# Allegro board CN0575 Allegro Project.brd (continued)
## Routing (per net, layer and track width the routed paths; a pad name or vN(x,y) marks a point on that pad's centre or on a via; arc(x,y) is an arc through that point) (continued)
UNNAMED_9_ADLTC9111_I40_LGATE2: length 20.7
  TOP w0.203: v1(22.89,14.77) 23.44,14.77 23.62,14.59 23.62,12.07 24.31,11.38 Q4.4 ; v1(20.38,24.58) 20.38,22.74 20.58,22.54 U1.8
  L3 PWR w0.203: v1(20.38,24.58) 20.37,24.58 20.37,16.46 22.06,14.77 v1(22.89,14.77)
UNNAMED_9_ADLTC9111_I40_SCCP: length 31
  TOP w0.203: U1.7 21.2,24.14 v1(21.65,24.58)
  L3 PWR w0.203: v1(21.65,24.58) 21.79,24.44 21.79,19.42 24.05,17.16 24.05,13.16 v1(24.57,12.65)
  BOTTOM w0.203: Q2.1 30.56,13.69 30.28,13.41 25.33,13.41 v1(24.57,12.65) 24.57,10.36 25.13,9.8 Q3.1
UNNAMED_9_CAP_I53_N1: length 1.6
  TOP w0.203: R16.2 C10.1
UNNAMED_9_CAP_I54_N1: length 2.6
  BOTTOM w0.635: R15.2 C9.1
UNNAMED_9_CAP_I80_N1: length 1.2
  BOTTOM w0.203: C12.1 18.65,15.48 R19.2
UNNAMED_9_CAPP_I72_N1: length 5.2
  TOP w0.762: C16.P 17.84,11.22 16.91,12.15 R20.2
UNNAMED_9_RES_I96_N1: length 2.3
  BOTTOM w0.203: Q2.2 28.42,16.76 R17.1
UNNAMED_9_RES_I97_N1: length 2.2
  BOTTOM w0.203: Q3.2 30.51,11.63 R18.1
UNNAMED_10_ADIN1110V2_I97_CEXT2: length 1.6
  TOP w0.203: C39.1 32.61,38.66 U3.19
UNNAMED_10_ADIN1110V2_I97_CEXT3: length 2.4
  TOP w0.203: C40.1 34.66,38.73 33.36,38.73 33.11,38.99 U3.20
UNNAMED_10_ADIN1110V2_I97_CLK25REF: length 51.5
  TOP w0.203: v1(53.78,34.68) 53.78,34.65 55.05,33.38 59.23,33.38 60.51,34.65 60.51,43.75 61.09,44.32 CLKOUT.1 ; U3.7 26.78,41.36 26.66,41.47 v1(26.22,41.47)
  L3 PWR w0.203: v1(26.22,41.47) 26.73,41.47 29.01,39.19 31.66,39.19 35.35,35.51 52.95,35.51 v1(53.78,34.68)
UNNAMED_10_ADIN1110V2_I97_DLDO1P1: length 39.5
  TOP w0.229: v1(34.54,41.09) 34.3,40.86 U3.23
  TOP w0.254: U3.24 34.27,41.36 v1(34.54,41.09)
  TOP w0.508: v1(34.54,41.09) 35.33,41.09 35.84,41.6 C32.1 ; UNK1.1V.1 61.48,47.62 60.65,48.46 v1(39.43,48.46)
  BOTTOM w0.508: v1(39.43,48.46) 39.43,42.67 38.23,41.47 37.04,41.47 C33.1 35.31,40.23 35.31,40.59 34.8,41.09 v1(34.54,41.09)
UNNAMED_10_ADIN1110V2_I97_LED0: length 38.3
  TOP w0.203: v1(26.57,43.98) 26.86,43.69 27.12,43.69 27.45,43.36 U3.3 ; LED0.C v1(54.03,40.46)
  L3 PWR w0.203: v1(54.03,40.46) 49.84,36.27 35.66,36.27 31.85,40.08 29.65,40.08 26.57,43.16 v1(26.57,43.98)
  BOTTOM w0.203: v1(26.57,43.98) 27.4,43.16 R31.2
UNNAMED_10_ADIN1110V2_I97_LED1: length 39.4
  TOP w0.203: U3.6 27.09,41.86 26.71,42.24 v1(26.22,42.24) ; LED1.C v1(54.03,38.68)
  L3 PWR w0.203: v1(26.22,42.24) 26.73,42.24 29.26,39.7 31.69,39.7 35.5,35.89 51.24,35.89 v1(54.03,38.68)
  BOTTOM w0.203: 26.87,40.57 27.18,40.88 27.18,40.98 ; 26.87,40.57 26.87,40.68 27.18,40.98 ; 26.87,40.57 26.38,40.08 26.21,40.08 R33.2 ; 27.18,40.98 27.18,41.97 26.91,42.24 v1(26.22,42.24)
UNNAMED_10_ADIN1110V2_I97_TEST1: length 3.2
  TOP w0.203: R29.2 34.92,43.88 34.91,43.88 34.48,43.45 34.48,42.63 34.21,42.36 U3.26
UNNAMED_10_DIOLED_I154_P: length 2
  TOP w0.203: LED0.A v1(58.42,40.46)
  BOTTOM w0.203: v1(58.42,40.46) R30.2
UNNAMED_10_DIOLED_I156_P: length 2
  TOP w0.203: LED1.A v1(58.42,38.68)
  BOTTOM w0.203: v1(58.42,38.68) R32.2
UNNAMED_10_NC2P_I58_N2: length 4.1
  BOTTOM w0.203: R34.2 35.31,45.15 35.31,48.23 35.52,48.43 JP3.2
UNNAMED_10_NC2P_I158_N2: length 2.6
  BOTTOM w0.203: R35.2 19.63,41.76 19.63,43.4 19.84,43.6 JP4.2
UNNAMED_10_NC2P_I159_N2: length 2.5
  BOTTOM w0.203: JP5.2 19.63,34.63 19.63,36.11 R36.2
UNNAMED_11_ADT75_I4_A0: length 18.2
  TOP w0.203: U4.7 v1(44.44,46.75)
  BOTTOM w0.203: JP8.2 40.77,35.17 40.41,35.54 40.41,41.1 40,41.51 40,45.88 40.87,46.75 v1(44.44,46.75)
UNNAMED_11_ADT75_I4_A1: length 9.1
  TOP w0.203: v1(44.88,43.64) 45.16,43.92 45.16,45.35 U4.6
  BOTTOM w0.203: v1(44.88,43.64) 44.88,39.78 44.28,39.18 JP7.2
UNNAMED_11_ADT75_I4_A2: length 9.5
  TOP w0.203: U4.5 45.67,45.36 45.67,43.48 44.48,42.3 42.32,42.3 v1(40.56,44.06)
  BOTTOM w0.203: JP6.2 v1(40.56,44.06)
UNNAMED_11_NC3PJMPR_I11_B: length 1.9
  BOTTOM w0.203: R42.1 43.67,36.01 JP8.3
UNNAMED_11_NC3PJMPR_I12_B: length 1.8
  BOTTOM w0.203: JP7.3 R41.1
UNNAMED_11_NC3PJMPR_I13_B: length 1.9
  BOTTOM w0.203: JP6.3 43.67,44.89 R40.1
VPD: length 29.4
  TOP w0.203: 25.36,21.54 24.8,21.54 24.8,21.54 U1.3 ; 25.36,21.54 25.96,20.94 C11.1 26.18,20.98 25.62,21.54 25.36,21.54
  TOP w0.762: C11.1 26.22,20.94 26.27,20.99 R16.1 29.2,20.99 29.96,20.23 v1(29.96,19.12) v1(29.96,18.49) 29.96,18.37 30.03,18.3 30.03,18.11 29.64,17.73 D3.C 29.52,17.73 29.52,17.85 29.27,18.1 29.27,18.3 29.33,18.35 v1(29.33,18.49) v1(29.33,19.12) 29.33,20.04 29.27,20.09 29.27,20.42 28.82,20.86 ; v1(29.33,8.07) 29.33,8.52 29.64,8.84 ; 29.64,8.84 29.96,8.52 v1(29.96,8.07) ; 29.64,8.84 D4.C
  BOTTOM w1.524: 17.02,9.78 D5.C 21.95,9.78 23.99,7.73 29.67,7.73
  vias: v1(29.33,7.44) v1(29.96,7.44)
XTALI: length 6
  TOP w0.203: Y1.1 22.6,41.3 23.02,40.89 24.98,40.89 C36.1 25.58,40.86 U3.8
XTALO: length 4.5
  TOP w0.203: U3.9 25.53,40.36 C37.1 23.67,40.1 Y1.3

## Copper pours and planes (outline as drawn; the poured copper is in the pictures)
3V3_POWER on BOTTOM: 54.48,41.48 54.48,35.89 56.95,35.89 56.95,41.48
3V3_POWER on L3 PWR: 58.9,32.23 39.88,32.23 37.31,29.67 1.65,29.67 1.65,55.63 64.36,55.63 64.36,34.9 61.57,34.9
5V_POWER on TOP: 9.53,41.05 5.44,41.05 5.01,41.47 5.01,48.06 5.38,48.44 10.11,48.44 10.16,48.49 10.16,49.94 10.41,50.19 12.04,50.19 12.5,49.73 12.5,41.47 12.12,41.09 12.12,39.22 10.24,39.22 10.22,39.24 10.22,40.35
5V_POWER on BOTTOM: 6.6,47.12 6.6,48.64 10.79,48.64 10.92,48.51 10.92,47.12 10.79,46.99 6.73,46.99
5V_POWER on BOTTOM: 8.25,49.91 8.25,49.15 8.13,49.02 8.13,48.54 6.6,48.54 6.6,54.48 7.37,55.24 12.06,55.24 12.32,54.99 12.32,53.59 12.06,53.34 8,53.34 7.75,53.09 7.75,50.42
GND on TOP: 42.82,1.27 1.27,1.27 1.27,27.61 1.27,27.64 37.31,27.64 38.48,26.47 38.48,20.98 39.83,19.63 42.82,19.63
GND on BOTTOM: 1.27,1.27 1.27,27.61 1.27,27.64 37.31,27.64 38.48,26.47 38.48,20.98 39.83,19.63 40.79,19.63 40.79,15.75 37.72,15.75 37.21,15.24 37.21,11.51 37.74,10.97 40.79,10.97 40.79,1.27
GND on L2 GND: 38.48,26.47 38.48,20.98 39.83,19.63 42.82,19.63 42.82,1.27 1.27,1.27 1.27,27.61 1.27,27.64 37.31,27.64
GND on L3 PWR: 1.27,1.27 1.27,27.62 1.27,27.64 37.31,27.64 38.48,26.47 38.48,20.98 39.83,19.63 42.82,19.63 42.82,1.27 40.31,1.27
GND_EARTH on TOP: 40.64,30.38 59.64,30.38 62.31,33.05 64.74,33.05 64.74,1.27 44.7,1.27 44.7,20.8 43.99,21.51 40.77,21.51 40.36,21.92 40.36,30.1
GND_EARTH on BOTTOM: 59.64,30.38 62.31,33.05 64.77,33.05 64.77,1.27 44.96,1.27 44.7,1.27 44.7,20.8 43.99,21.51 40.77,21.51 40.36,21.92 40.36,30.1 40.64,30.38 ; 1 cut-out
GND_EARTH on L2 GND: 40.64,30.38 59.64,30.38 62.31,33.05 64.77,33.05 64.77,1.27 44.7,1.27 44.7,20.8 43.99,21.51 40.77,21.51 40.36,21.92 40.36,30.1 ; 1 cut-out
GND_EARTH on L3 PWR: 40.64,30.38 59.64,30.38 62.31,33.05 64.77,33.05 64.77,1.27 44.7,1.27 44.7,20.8 43.99,21.51 40.77,21.51 40.36,21.92 40.36,30.1 ; 1 cut-out
GND_ISO on TOP: 1.27,56.01 64.77,56.01 64.77,34.9 61.57,34.9 58.9,32.23 39.88,32.23 37.31,29.67 1.27,29.67
GND_ISO on BOTTOM: 1.27,56.01 64.77,56.01 64.77,35.08 64.77,34.9 61.57,34.9 58.9,32.23 39.88,32.23 37.31,29.67 1.27,29.67
GND_ISO on L2 GND: 1.27,56.01 64.77,56.01 64.77,34.9 61.57,34.9 58.9,32.23 39.88,32.23 37.31,29.67 1.27,29.67
DIFF_N on TOP: 42.82,19.53 42.82,14.02 39.75,14.02 39.75,15.24 40.79,15.24 40.79,19.53
DIFF_N on BOTTOM: 34.32,21.78 37.77,21.78 37.77,20.37 35.94,20.37 37.49,18.82 37.49,15.7 37.95,15.24 40.79,15.24 40.79,14.02 37.82,14.02 36.55,15.29 36.55,18.39 34.32,20.62
DIFF_P on TOP: 42.82,12.73 39.75,12.73 39.75,11.48 40.79,11.48 40.79,7.01 42.82,7.01
DIFF_P on BOTTOM: 30,21.79 33.48,21.79 33.48,20.29 36.07,17.7 36.07,14.63 37.97,12.73 40.79,12.73 40.79,11.48 37.82,11.48 35.26,14.05 35.26,17.25 32.23,20.27 30,20.27
LT8304_VIN on TOP: 2.46,20.55 2.46,10.69 2.54,10.62 8.82,10.62 10.34,9.09 15.04,9.09 15.57,9.62 15.57,13.82 13.93,13.82 13.52,13.41 10.22,13.41 9.58,12.77 5.14,12.77 4.38,13.53 4.38,17.18 6.1,17.17 6.1,21.46 3.38,21.46
LT8304_VIN on BOTTOM: 2.08,22.61 7.7,22.61 7.7,19.79 4.67,19.79 4.67,17.91 7.44,17.91 7.44,16.48 3.61,16.48 3.61,12.32 11.05,12.32 12.93,10.44 15.01,10.44 15.01,8.61 13.26,8.61 12.95,8.92 2.08,8.92
PD_IN1 on TOP: 31.68,18.23 31.68,15.88 31.24,15.44 27.84,15.44 27.84,13.61 33.14,13.61 33.14,14.87 33.82,15.54 39.24,15.54 39.24,19 37.36,19 37.36,18.49 31.93,18.49
PD_IN1 on BOTTOM: 32.05,15.32 34.34,15.32 34.75,15.72 34.75,17.14 34.19,17.7 32.05,17.7
PD_IN1 on L3 PWR: 24.31,20.39 25.2,19.5 25.2,19.25 25.08,19.12 23.81,19.12 23.17,19.76 23.17,22.17 24.29,23.29 33.12,23.29 35.28,21.13 35.28,15.04 33.3,15.04 33.3,21.06 32.31,22.04 24.82,22.04 24.31,21.54
PD_IN2 on TOP: 31.68,8.33 31.68,10.68 31.24,11.12 31.24,11.13 27.84,11.13 27.84,12.95 33.14,12.95 33.14,11.69 33.81,11.02 39.24,11.02 39.24,7.04 37.31,7.04 37.31,8.07 31.93,8.07
PD_IN2 on BOTTOM: 32.08,11.25 34.37,11.25 34.77,10.85 34.77,9.42 34.21,8.86 32.08,8.86
PD_IN2 on L3 PWR: 24.82,21.28 24.82,20.65 25.46,20.01 30.36,20.01 30.81,19.56 30.81,8.53 34.37,8.53 34.37,9.93 32.79,11.51 32.79,20.57 31.83,21.54 25.08,21.54
VPD on BOTTOM (solid shape): 18.13,8.58 15.38,8.58 15.38,11.13 18.13,11.13
VPD on TOP: 30.41,17.15 30.41,20.39 29.33,21.47 25.78,21.47 25.78,20.65 28.51,20.65 28.82,20.33 28.82,17.15 28.95,17.03 30.28,17.03
VPD on TOP: 28.82,9.41 28.82,6.61 28.89,6.55 30.35,6.55 30.41,6.61 30.41,9.41 30.28,9.53 28.95,9.53
VPD on BOTTOM: 28.98,8.41 28.98,7.06 30.35,7.06 30.35,8.41
VPD on L3 PWR: 27.49,19.41 30.2,19.41 30.3,19.3 30.3,7.09 28.68,7.09 27.36,8.4 27.36,19.28

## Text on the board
Ref Des/Assembly Bottom: C | A
Ref Des/Silkscreen Bottom: A | C | SECONDARY SIDE | 08-068269 REV C Z | S
User.Comments: 4.    RoHS COMPLIANCE: ASSEMBLY VENDOR SHOULD ASSURE COMPLIANCE | 5.    BOARDS TO BE SHIPPED SINGULATED AFTER ASSEMBLY PROCESS. | WITH LEAD-FREE AND RoHS PCB ASSEMBLY STANDARDS (EU RoHS | DIRECTIVE 2002/95/EC). | SMOOTHEN EDGES AND FREE FROM BURRS AFTER DEPANELIZATION PROCESS. | 8.    INSTALL JUMPER SHUNT (M023139) ON THE FOLLOWING LOCATIONS: | 7.    ADD SOLDER BLOB ON THE FOLLOWING LOCATIONS: | 6.    ADD SOLDER BLOB FOR PINS 2 & 3 ON THE FOLLOWING LOCATIONS: | - JP1 (PIN 2 & 3) | - JP2 (PIN 1 & 2) | - JP9 | - JP10 | - JP4 | - JP5 | - JP6 | - JP7 | - JP8 | - JP14 | - JP11 | - JP12 | - JP13 | - JP15 | - JP16
Ref Des/Assembly Top: C | A
Ref Des/Silkscreen Top: C | A | 08-068269 REV C Z | EVAL-CN0575-RPIZ | PRIMARY SIDE
PAGE_OUTLINE: N/A | N.BUENAFLOR | B | C | CHANGES PER ECR-109978 | CHANGES PER ECR-112290 | 08OCT22 | 28DEC22 | A. UY | CUSTOMER EVALUATION Z
BODY_CENTER: ROHS COMPLIANCE NOTE: | THE EU RoHS DIRECTIVE 2002/95/EC | HOMOGENOUS MATERIALS IN THIS BOARD SHALL BE COMPLIANT | 15.    BOARDS TO BE SHIPPED IN ARRAYS. | PANEL TO BE SUBJECTED TO CUSTOMER'S APPROVAL. | PANELED SOLDER PASTE STENCIL SHOULD BE SENT TO THE CUSTOMER.
DIMENSION: (REF) | (BOARD CORNERS) | DIA MAX
User.12: DETAIL A | SEE DETAIL A
User.17: L2 GND | 08-      -07
User.18: L3 PWR | 08-      -08
User.19: 08-      -08 | L3 PWR
User.45: FIGURE | SIZE | 10.0 | 35.0 | 40.0 | 45.0 | 125.0 | DRILL CHART: TOP to BOTTOM | FINISHED HOLES IN MILS | PLATED | NON-PLATED | QTY | 465 | 15 | 4 | 43 | TOLERANCE/NOTES
